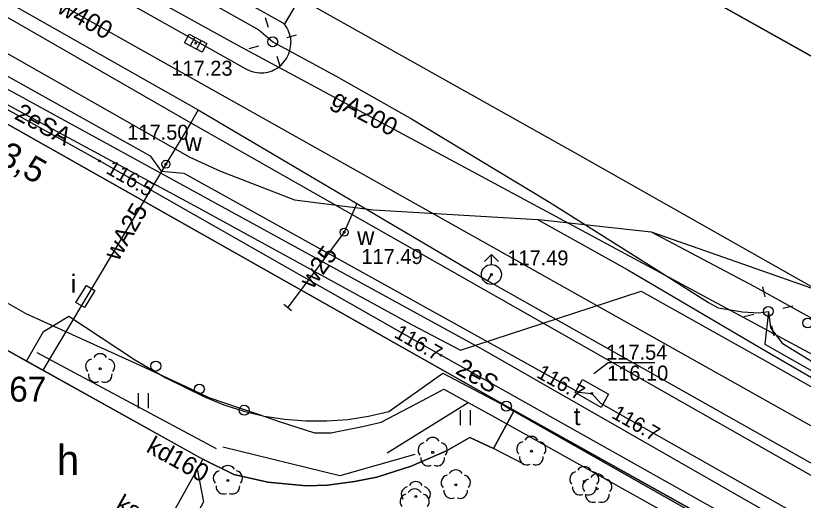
# Model space of a CAD drawing. Extents: x 6434771 to 6436222, y 5663454 to 5664782.
# Drawn here: x 6435316.51 to 6435355.97, y 5663796.64 to 5663820.92 of the extents above; entities that cross this region are included whole.
import ezdxf

# ---------------------------------------------------------------- set-up
doc = ezdxf.new("R2010")
doc.units = 0
for name, color, linetype in [('Warstwa 1', 7, 'Continuous'), ('Warstwa 10', 7, 'Continuous'), ('Warstwa 11', 7, 'Continuous'), ('Warstwa 12', 7, 'Continuous'), ('Warstwa 13', 7, 'Continuous'), ('Warstwa 14', 7, 'Continuous'), ('Warstwa 2', 7, 'Continuous'), ('Warstwa 20', 7, 'Continuous'), ('Warstwa 3', 7, 'Continuous'), ('Warstwa 4', 7, 'Continuous'), ('Warstwa 5', 7, 'Continuous'), ('Warstwa 6', 7, 'Continuous'), ('Warstwa 7', 7, 'Continuous'), ('Warstwa 8', 7, 'Continuous'), ('Warstwa 9', 7, 'Continuous')]:
    doc.layers.add(name, color=color, linetype=linetype)

msp = doc.modelspace()

# ---------------------------------------------------------------- linework, layer by layer
at = {"layer": 'Warstwa 1'}
for p, q in [((6435284.269, 5663833.48), (6435341.096, 5663801.352)), ((6435284.269, 5663833.48), (6435341.096, 5663801.352)), ((6435341.096, 5663801.352), (6435379.471, 5663779.947)), ((6435341.096, 5663801.352), (6435379.471, 5663779.947))]:
    msp.add_line(p, q, dxfattribs=at)
msp.add_lwpolyline([(6435315.15, 5663804.67), (6435325.88, 5663798.7), (6435322.44, 5663792.51), (6435311.73, 5663798.5), (6435312.37, 5663799.67), (6435312.69, 5663800.25), (6435314.19, 5663802.94), (6435314.51, 5663803.52)], close=True, dxfattribs=at)
for centre in [(6435323.53, 5663803.36), (6435325.71, 5663802.21), (6435327.96, 5663801.15)]:
    msp.add_circle(centre, 0.25, dxfattribs=at)
at = {"layer": 'Warstwa 10'}
for points in [[(6435276.398, 5663847.572), (6435285.481, 5663842.407), (6435289.025, 5663840.412), (6435288.717, 5663836.154), (6435288.46, 5663831.396), (6435296.942, 5663826.797), (6435314.148, 5663817.497), (6435325.665, 5663811.286), (6435336.38, 5663805.426), (6435338.792, 5663804.166), (6435347.854, 5663807.111), (6435354.232, 5663803.535), (6435364.384, 5663797.782), (6435371.56, 5663793.64)], [(6435362.27, 5663788.69), (6435362.41, 5663788.96), (6435362.84, 5663789.86), (6435340.58, 5663802.36), (6435337.82, 5663803.9), (6435320.71, 5663813.64), (6435309.18, 5663820.04), (6435307.2, 5663820.8), (6435302.95, 5663823.03), (6435301.33, 5663824.12), (6435299.2, 5663826.42), (6435293.53, 5663831.99), (6435290.73, 5663834.08), (6435287.63, 5663836.01), (6435276.336, 5663842.501)]]:
    msp.add_lwpolyline(points, dxfattribs=at)
msp.add_circle((6435341.096, 5663801.352), 0.25, dxfattribs=at)
msp.add_circle((6435341.096, 5663801.352), 0.25, dxfattribs=at)
at = {"layer": 'Warstwa 11'}
for centre in [(6435320.74, 5663803.23), (6435337.404, 5663799.038), (6435342.35, 5663799.09), (6435327.14, 5663797.63), (6435338.56, 5663797.41), (6435345, 5663797.58), (6435345.65, 5663797.21), (6435336.56, 5663796.82)]:
    msp.add_circle(centre, 0.05, dxfattribs=at)
for centre, start, end in [((6435320.383, 5663803.346), 102.1471, 221.8529), ((6435320.74, 5663803.605), 30.1471, 149.8529), ((6435321.097, 5663803.346), 318.1471, 77.8529), ((6435320.52, 5663802.927), 174.1471, 293.8529), ((6435320.96, 5663802.927), 246.1471, 5.8529), ((6435337.404, 5663799.413), 30.1471, 149.8529), ((6435342.35, 5663799.465), 30.1471, 149.8529), ((6435337.047, 5663799.154), 102.1471, 221.8529), ((6435337.761, 5663799.154), 318.1471, 77.8529), ((6435341.993, 5663799.206), 102.1471, 221.8529), ((6435342.707, 5663799.206), 318.1471, 77.8529), ((6435337.184, 5663798.735), 174.1471, 293.8529), ((6435337.624, 5663798.735), 246.1471, 5.8529), ((6435342.13, 5663798.787), 174.1471, 293.8529), ((6435342.57, 5663798.787), 246.1471, 5.8529), ((6435326.783, 5663797.746), 102.1471, 221.8529), ((6435327.14, 5663798.005), 30.1471, 149.8529), ((6435327.497, 5663797.746), 318.1471, 77.8529), ((6435338.56, 5663797.785), 30.1471, 149.8529), ((6435345, 5663797.955), 30.1471, 149.8529), ((6435338.203, 5663797.526), 102.1471, 221.8529), ((6435338.917, 5663797.526), 318.1471, 77.8529), ((6435344.643, 5663797.696), 102.1471, 221.8529), ((6435345.65, 5663797.585), 30.1471, 149.8529), ((6435345.357, 5663797.696), 318.1471, 77.8529), ((6435326.92, 5663797.327), 174.1471, 293.8529), ((6435327.36, 5663797.327), 246.1471, 5.8529), ((6435336.56, 5663797.195), 30.1471, 149.8529), ((6435344.78, 5663797.277), 174.1471, 293.8529), ((6435345.293, 5663797.326), 102.1471, 221.8529), ((6435345.22, 5663797.277), 246.1471, 5.8529), ((6435346.007, 5663797.326), 318.1471, 77.8529), ((6435336.143, 5663796.576), 102.1471, 221.8529), ((6435336.203, 5663796.936), 102.1471, 221.8529), ((6435336.5, 5663796.835), 30.1471, 149.8529), ((6435336.857, 5663796.576), 318.1471, 77.8529), ((6435336.917, 5663796.936), 318.1471, 77.8529), ((6435338.34, 5663797.107), 174.1471, 293.8529), ((6435338.78, 5663797.107), 246.1471, 5.8529), ((6435345.43, 5663796.907), 174.1471, 293.8529), ((6435345.87, 5663796.907), 246.1471, 5.8529)]:
    msp.add_arc(centre, 0.375, start, end, dxfattribs=at)
at = {"layer": 'Warstwa 12'}
for points in [[(6435496.272, 5663731.55), (6435494.673, 5663731.954), (6435441.98, 5663757.861), (6435431.505, 5663763.318), (6435395.21, 5663783.064), (6435393.025, 5663784.254), (6435327.584, 5663819.466), (6435304.485, 5663832.195), (6435292.223, 5663838.764), (6435285.521, 5663842.735), (6435276.408, 5663848.377)], [(6435276.372, 5663845.49), (6435313.12, 5663824.65), (6435397.7, 5663777.16), (6435400.08, 5663771.33), (6435444.75, 5663747.22)], [(6435276.356, 5663844.113), (6435325.654, 5663816.199), (6435333.608, 5663811.513), (6435340.162, 5663807.633), (6435364.946, 5663793.663), (6435394.798, 5663777.062), (6435394.937, 5663776.984)], [(6435286.42, 5663844), (6435287.35, 5663843.455), (6435292.961, 5663840.318), (6435298.714, 5663837.138), (6435303.419, 5663834.605), (6435305.745, 5663833.419), (6435306.683, 5663832.532), (6435308.014, 5663831.992), (6435310.819, 5663830.397), (6435322.822, 5663823.509), (6435328.691, 5663820.214), (6435329.386, 5663819.611), (6435332.564, 5663817.88), (6435336.345, 5663815.743), (6435343.262, 5663811.567), (6435348.084, 5663808.529), (6435351.234, 5663806.553), (6435351.715, 5663806.277), (6435352.923, 5663806.074), (6435353.729, 5663806.037), (6435354.225, 5663806.103)], [(6435276.308, 5663840.167), (6435285.47, 5663834.8), (6435286.134, 5663834.744), (6435286.62, 5663834.35), (6435323.25, 5663813.89), (6435323.79, 5663813.12), (6435324.94, 5663813.03), (6435344.71, 5663802.06), (6435345.376, 5663801.99), (6435345.82, 5663801.51), (6435374.05, 5663785.53), (6435381.33, 5663787.82), (6435417.36, 5663768.01), (6435438.98, 5663755.98), (6435463.27, 5663743.33), (6435463.498, 5663743.152), (6435463.77, 5663743.07), (6435464.82, 5663742.52), (6435490.42, 5663730.15), (6435500.39, 5663725.18)], [(6435276.296, 5663839.122), (6435282.733, 5663835.528), (6435283.155, 5663835.293), (6435283.578, 5663835.058), (6435339.95, 5663804.176), (6435373.154, 5663785.164), (6435373.6, 5663784.903), (6435374.09, 5663784.842), (6435381.569, 5663787.202), (6435381.966, 5663786.947), (6435382.363, 5663786.692), (6435416.468, 5663767.82), (6435452.468, 5663747.664), (6435497.181, 5663726.003), (6435502.116, 5663724.694), (6435541.028, 5663706.294), (6435541.516, 5663706.079), (6435555.51, 5663699.69), (6435571.692, 5663693.874), (6435578.552, 5663690.422)], [(6435293.228, 5663834.004), (6435325.286, 5663815.553), (6435364.64, 5663793.187), (6435394.601, 5663776.514), (6435437.403, 5663753.976), (6435437.705, 5663753.871), (6435459.328, 5663743.372)], [(6435325.654, 5663816.199), (6435325.286, 5663815.553), (6435324.031, 5663813.478), (6435317.862, 5663803.161)], [(6435301.381, 5663814.818), (6435304.531, 5663813.026), (6435312.56, 5663808.528), (6435317.022, 5663805.997), (6435322.544, 5663803.492), (6435325.031, 5663802.332), (6435326.182, 5663801.779), (6435327.709, 5663801.276), (6435328.664, 5663800.945), (6435329.709, 5663800.582), (6435331.487, 5663800.019), (6435332.294, 5663800.009), (6435333.884, 5663800.34), (6435334.816, 5663800.546), (6435336.575, 5663801.467), (6435337.956, 5663802.205), (6435340.361, 5663800.883), (6435352.831, 5663793.927), (6435371.59, 5663783.486), (6435371.373, 5663781.121), (6435370.67, 5663774.08)], [(6435333.608, 5663811.513), (6435332.961, 5663810.07), (6435330.135, 5663806.284)], [(6435340.162, 5663807.633), (6435340.346, 5663807.951)], [(6435354.225, 5663806.103), (6435354.045, 5663804.455)], [(6435354.225, 5663806.103), (6435354.045, 5663804.455), (6435378.698, 5663790.467), (6435402.889, 5663777.914), (6435418.826, 5663768.461), (6435428.67, 5663762.922)], [(6435354.225, 5663806.103), (6435354.339, 5663805.276), (6435354.921, 5663804.516), (6435356.256, 5663803.692), (6435357.591, 5663802.815), (6435361.586, 5663800.407), (6435364.82, 5663798.645), (6435367.626, 5663797.157), (6435374.185, 5663793.482), (6435378.033, 5663791.335), (6435380.136, 5663790.212), (6435385.102, 5663787.109), (6435386.865, 5663786.012), (6435388.176, 5663785.377), (6435390.525, 5663783.895), (6435393.123, 5663782.317), (6435393.63, 5663781.962), (6435398.309, 5663779.51), (6435408.093, 5663774.465), (6435411.635, 5663772.573), (6435418.397, 5663768.965), (6435423.022, 5663766.513), (6435428.828, 5663763.443)]]:
    msp.add_lwpolyline(points, dxfattribs=at)
at = {"layer": 'Warstwa 14'}
msp.add_lwpolyline([(6435348.529, 5663803.532), (6435346.196, 5663803.532), (6435345.484, 5663802.965)], dxfattribs=at)
for centre in [(6435320.71, 5663813.64), (6435337.82, 5663803.9), (6435345.376, 5663801.99), (6435345.376, 5663801.99), (6435345.376, 5663801.99)]:
    msp.add_circle(centre, 0.045, dxfattribs=at)
at = {"layer": 'Warstwa 2'}
msp.add_line((6435341.026, 5663801.362), (6435372.62, 5663783.46), dxfattribs=at)
for points in [[(6435341.476, 5663801.109), (6435340.455, 5663799.23)], [(6435340.455, 5663799.23), (6435339.262, 5663799.789), (6435338.088, 5663799.109), (6435336.324, 5663798.343), (6435334.597, 5663797.798), (6435333.487, 5663797.579), (6435332.134, 5663797.4), (6435331.061, 5663797.354), (6435329.135, 5663797.539), (6435327.431, 5663797.929), (6435325.88, 5663798.7)], [(6435341.97, 5663798.449), (6435340.455, 5663799.23)]]:
    msp.add_lwpolyline(points, dxfattribs=at)
for centre in [(6435329.386, 5663819.611), (6435354.225, 5663806.103), (6435356.2, 5663805.52)]:
    msp.add_circle(centre, 0.25, dxfattribs=at)
at = {"layer": 'Warstwa 20'}
msp.add_line((6435330.327, 5663806.124), (6435329.943, 5663806.444), dxfattribs=at)
at = {"layer": 'Warstwa 4'}
for p, q in [((6435325.49, 5663819.844), (6435325.252, 5663819.404)), ((6435325.798, 5663819.678), (6435325.56, 5663819.238))]:
    msp.add_line(p, q, dxfattribs=at)
for points in [[(6435329.174, 5663820.33), (6435329.032, 5663820.81)], [(6435330.105, 5663819.823), (6435330.585, 5663819.965)], [(6435328.667, 5663819.399), (6435328.187, 5663819.257)], [(6435329.598, 5663818.892), (6435329.74, 5663818.412)], [(6435339.992, 5663808.597), (6435340.346, 5663808.951)], [(6435340.7, 5663808.597), (6435340.346, 5663808.951)], [(6435340.346, 5663808.451), (6435340.346, 5663808.951)], [(6435320.474, 5663807.146), (6435319.953, 5663806.293), (6435319.526, 5663806.554), (6435320.047, 5663807.407), (6435320.474, 5663807.146)], [(6435354.063, 5663806.835), (6435353.956, 5663807.324)], [(6435354.957, 5663806.265), (6435355.446, 5663806.372)], [(6435353.493, 5663805.941), (6435353.004, 5663805.834)], [(6435354.387, 5663805.371), (6435354.494, 5663804.882)], [(6435326.577, 5663799.218), (6435317.577, 5663804.024)], [(6435339.183, 5663801.526), (6435335.123, 5663798.996)], [(6435336.51, 5663798.929), (6435332.749, 5663797.868), (6435326.894, 5663799.293)]]:
    msp.add_lwpolyline(points, dxfattribs=at)
for points in [[(6435325.204, 5663819.999), (6435326.084, 5663819.523), (6435325.846, 5663819.083), (6435324.966, 5663819.559)], [(6435344.539, 5663802.034), (6435344.909, 5663802.686), (6435346.213, 5663801.946), (6435345.843, 5663801.294)]]:
    msp.add_lwpolyline(points, close=True, dxfattribs=at)
for centre, radius in [((6435324.031, 5663813.478), 0.2), ((6435332.961, 5663810.07), 0.2), ((6435340.346, 5663807.951), 0.5)]:
    msp.add_circle(centre, radius, dxfattribs=at)
at = {"layer": 'Warstwa 5'}
for p, q in [((6435345.423, 5663825.041), (6435393.413, 5663798.15)), ((6435317.9, 5663805.1), (6435319.17, 5663805.86)), ((6435319.17, 5663805.86), (6435322.507, 5663803.664)), ((6435317.048, 5663803.614), (6435317.9, 5663805.1)), ((6435322.507, 5663803.664), (6435324.025, 5663802.777)), ((6435317.048, 5663803.614), (6435325.88, 5663798.7)), ((6435335.212, 5663801.083), (6435337.906, 5663803.01)), ((6435337.906, 5663803.01), (6435341.026, 5663801.362)), ((6435324.025, 5663802.777), (6435325.022, 5663802.286)), ((6435325.022, 5663802.286), (6435325.963, 5663801.816)), ((6435322.667, 5663801.249), (6435322.667, 5663801.999)), ((6435323.167, 5663801.249), (6435323.167, 5663801.999)), ((6435325.963, 5663801.816), (6435326.937, 5663801.421)), ((6435326.937, 5663801.421), (6435327.938, 5663801.101)), ((6435341.026, 5663801.362), (6435341.475, 5663801.107)), ((6435327.938, 5663801.101), (6435328.961, 5663800.859)), ((6435334.188, 5663800.846), (6435335.212, 5663801.083)), ((6435338.797, 5663800.398), (6435338.797, 5663801.148)), ((6435339.297, 5663800.398), (6435339.297, 5663801.148)), ((6435340.455, 5663799.23), (6435341.475, 5663801.107)), ((6435328.961, 5663800.859), (6435330, 5663800.695)), ((6435330, 5663800.695), (6435331.048, 5663800.612)), ((6435331.048, 5663800.612), (6435332.1, 5663800.61)), ((6435332.1, 5663800.61), (6435333.148, 5663800.688)), ((6435333.148, 5663800.688), (6435334.188, 5663800.846)), ((6435338.088, 5663799.109), (6435339.262, 5663799.789)), ((6435339.262, 5663799.789), (6435340.455, 5663799.23)), ((6435336.324, 5663798.343), (6435338.088, 5663799.109)), ((6435325.88, 5663798.7), (6435327.431, 5663797.929)), ((6435334.597, 5663797.798), (6435336.324, 5663798.343)), ((6435327.431, 5663797.929), (6435329.135, 5663797.539)), ((6435333.487, 5663797.579), (6435334.597, 5663797.798)), ((6435329.135, 5663797.539), (6435331.061, 5663797.354)), ((6435331.061, 5663797.354), (6435332.134, 5663797.4)), ((6435332.134, 5663797.4), (6435333.487, 5663797.579))]:
    msp.add_line(p, q, dxfattribs=at)
at = {"layer": 'Warstwa 6'}
for points in [[(6435557.624, 5663617.186), (6435560.245, 5663620.878), (6435595.767, 5663670.923), (6435531.111, 5663701.684), (6435473.15, 5663729.463), (6435470.997, 5663730.839), (6435385.94, 5663776.469), (6435383.505, 5663771.998), (6435381.775, 5663772.849), (6435379.415, 5663768.737), (6435374.588, 5663771.455), (6435379.471, 5663779.947), (6435341.096, 5663801.352), (6435284.269, 5663833.48), (6435246.778, 5663854.403), (6435242.169, 5663846.309), (6435237.4, 5663848.916), (6435241.929, 5663857.022), (6435210.691, 5663874.851), (6435202.784, 5663879.266), (6435199.977, 5663874.56), (6435180.355, 5663839.798)], [(6435246.778, 5663854.403), (6435284.269, 5663833.48), (6435341.096, 5663801.352), (6435379.471, 5663779.947)], [(6435345.423, 5663825.041), (6435393.413, 5663798.15)]]:
    msp.add_lwpolyline(points, dxfattribs=at)
for centre in [(6435325.525, 5663819.541), (6435324.031, 5663813.478), (6435332.961, 5663810.07), (6435340.346, 5663807.951), (6435345.376, 5663801.99)]:
    msp.add_circle(centre, 0.045, dxfattribs=at)
at = {"layer": 'Warstwa 7'}
msp.add_lwpolyline([(6435325.601, 5663798.197), (6435325.92, 5663796.56), (6435323.243, 5663791.591)], dxfattribs=at)
at = {"layer": 'Warstwa 8'}
for p, q in [((6435321.639, 5663825.164), (6435329.895, 5663820.569)), ((6435345.423, 5663825.041), (6435393.413, 5663798.15)), ((6435319.462, 5663823.08), (6435328.012, 5663818.275)), ((6435311.189, 5663821.796), (6435325.241, 5663813.829)), ((6435329.973, 5663820.476), (6435330.747, 5663821.797)), ((6435329.974, 5663820.476), (6435330.747, 5663821.797)), ((6435330.747, 5663821.797), (6435344.539, 5663814.043)), ((6435330.747, 5663821.797), (6435344.539, 5663814.043)), ((6435329.895, 5663820.569), (6435329.965, 5663820.487)), ((6435329.965, 5663820.487), (6435329.974, 5663820.476)), ((6435329.973, 5663820.476), (6435330.029, 5663820.401)), ((6435330.029, 5663820.401), (6435330.087, 5663820.311)), ((6435330.087, 5663820.311), (6435330.138, 5663820.216)), ((6435330.138, 5663820.216), (6435330.182, 5663820.118)), ((6435330.182, 5663820.118), (6435330.218, 5663820.018)), ((6435330.218, 5663820.018), (6435330.248, 5663819.914)), ((6435330.248, 5663819.914), (6435330.27, 5663819.81)), ((6435330.27, 5663819.81), (6435330.285, 5663819.703)), ((6435330.282, 5663819.382), (6435330.291, 5663819.489)), ((6435330.285, 5663819.703), (6435330.292, 5663819.596)), ((6435330.291, 5663819.489), (6435330.292, 5663819.596)), ((6435330.173, 5663818.968), (6435330.212, 5663819.069)), ((6435330.212, 5663819.069), (6435330.243, 5663819.171)), ((6435330.243, 5663819.171), (6435330.266, 5663819.276)), ((6435330.266, 5663819.276), (6435330.282, 5663819.382)), ((6435329.952, 5663818.602), (6435330.017, 5663818.688)), ((6435330.017, 5663818.688), (6435330.076, 5663818.777)), ((6435330.076, 5663818.777), (6435330.128, 5663818.871)), ((6435330.128, 5663818.871), (6435330.173, 5663818.968)), ((6435328.012, 5663818.275), (6435328.106, 5663818.222)), ((6435329.451, 5663818.206), (6435329.545, 5663818.257)), ((6435329.545, 5663818.257), (6435329.636, 5663818.314)), ((6435329.636, 5663818.314), (6435329.723, 5663818.377)), ((6435329.723, 5663818.377), (6435329.805, 5663818.447)), ((6435329.805, 5663818.447), (6435329.881, 5663818.522)), ((6435329.881, 5663818.522), (6435329.952, 5663818.602)), ((6435328.106, 5663818.222), (6435328.203, 5663818.176)), ((6435328.203, 5663818.176), (6435328.303, 5663818.138)), ((6435328.303, 5663818.138), (6435328.405, 5663818.106)), ((6435328.405, 5663818.106), (6435328.51, 5663818.082)), ((6435328.51, 5663818.082), (6435328.616, 5663818.065)), ((6435328.616, 5663818.065), (6435328.723, 5663818.056)), ((6435328.723, 5663818.056), (6435328.83, 5663818.055)), ((6435328.83, 5663818.055), (6435328.937, 5663818.062)), ((6435328.937, 5663818.062), (6435329.044, 5663818.076)), ((6435329.044, 5663818.076), (6435329.149, 5663818.097)), ((6435329.149, 5663818.097), (6435329.252, 5663818.126)), ((6435329.252, 5663818.126), (6435329.353, 5663818.163)), ((6435329.353, 5663818.163), (6435329.451, 5663818.206)), ((6435344.539, 5663814.043), (6435356.736, 5663807.152)), ((6435344.539, 5663814.043), (6435356.736, 5663807.152)), ((6435325.241, 5663813.829), (6435326.77, 5663813.12)), ((6435326.77, 5663813.12), (6435330.48, 5663811.69)), ((6435330.48, 5663811.69), (6435334.43, 5663811.19)), ((6435334.43, 5663811.19), (6435342.655, 5663810.708)), ((6435342.655, 5663810.708), (6435342.727, 5663810.704)), ((6435342.727, 5663810.704), (6435348.36, 5663810.08)), ((6435348.36, 5663810.08), (6435350.684, 5663809.278)), ((6435350.684, 5663809.278), (6435356.736, 5663807.152))]:
    msp.add_line(p, q, dxfattribs=at)
at = {"layer": 'Warstwa 9'}
for p, q in [((6435321.639, 5663825.164), (6435329.895, 5663820.569)), ((6435319.462, 5663823.08), (6435328.012, 5663818.275)), ((6435311.189, 5663821.796), (6435325.241, 5663813.829)), ((6435329.895, 5663820.569), (6435329.965, 5663820.487)), ((6435329.965, 5663820.487), (6435329.973, 5663820.476)), ((6435329.973, 5663820.476), (6435330.029, 5663820.401)), ((6435330.029, 5663820.401), (6435330.087, 5663820.311)), ((6435330.087, 5663820.311), (6435330.138, 5663820.216)), ((6435330.138, 5663820.216), (6435330.182, 5663820.118)), ((6435330.182, 5663820.118), (6435330.218, 5663820.018)), ((6435330.218, 5663820.018), (6435330.248, 5663819.914)), ((6435330.248, 5663819.914), (6435330.27, 5663819.81)), ((6435330.27, 5663819.81), (6435330.285, 5663819.703)), ((6435330.282, 5663819.382), (6435330.291, 5663819.489)), ((6435330.285, 5663819.703), (6435330.292, 5663819.596)), ((6435330.291, 5663819.489), (6435330.292, 5663819.596)), ((6435330.173, 5663818.968), (6435330.212, 5663819.069)), ((6435330.212, 5663819.069), (6435330.243, 5663819.171)), ((6435330.243, 5663819.171), (6435330.266, 5663819.276)), ((6435330.266, 5663819.276), (6435330.282, 5663819.382)), ((6435329.952, 5663818.602), (6435330.017, 5663818.688)), ((6435330.017, 5663818.688), (6435330.076, 5663818.777)), ((6435330.076, 5663818.777), (6435330.128, 5663818.871)), ((6435330.128, 5663818.871), (6435330.173, 5663818.968)), ((6435328.012, 5663818.275), (6435328.106, 5663818.222)), ((6435329.451, 5663818.206), (6435329.545, 5663818.257)), ((6435329.545, 5663818.257), (6435329.636, 5663818.314)), ((6435329.636, 5663818.314), (6435329.723, 5663818.377)), ((6435329.723, 5663818.377), (6435329.805, 5663818.447)), ((6435329.805, 5663818.447), (6435329.881, 5663818.522)), ((6435329.881, 5663818.522), (6435329.952, 5663818.602)), ((6435328.106, 5663818.222), (6435328.203, 5663818.176)), ((6435328.203, 5663818.176), (6435328.303, 5663818.138)), ((6435328.303, 5663818.138), (6435328.405, 5663818.106)), ((6435328.405, 5663818.106), (6435328.51, 5663818.082)), ((6435328.51, 5663818.082), (6435328.616, 5663818.065)), ((6435328.616, 5663818.065), (6435328.723, 5663818.056)), ((6435328.723, 5663818.056), (6435328.83, 5663818.055)), ((6435328.83, 5663818.055), (6435328.937, 5663818.062)), ((6435328.937, 5663818.062), (6435329.044, 5663818.076)), ((6435329.044, 5663818.076), (6435329.149, 5663818.097)), ((6435329.149, 5663818.097), (6435329.252, 5663818.126)), ((6435329.252, 5663818.126), (6435329.353, 5663818.163)), ((6435329.353, 5663818.163), (6435329.451, 5663818.206)), ((6435325.241, 5663813.829), (6435326.77, 5663813.12)), ((6435326.77, 5663813.12), (6435330.48, 5663811.69)), ((6435330.48, 5663811.69), (6435334.43, 5663811.19)), ((6435334.43, 5663811.19), (6435342.655, 5663810.708)), ((6435342.655, 5663810.708), (6435347.176, 5663808.176)), ((6435348.36, 5663810.08), (6435350.684, 5663809.278)), ((6435348.36, 5663810.08), (6435353.534, 5663807.343)), ((6435350.684, 5663809.278), (6435356.736, 5663807.152)), ((6435347.176, 5663808.176), (6435353.795, 5663804.286)), ((6435353.534, 5663807.343), (6435359.939, 5663803.801)), ((6435317.9, 5663805.1), (6435319.17, 5663805.86)), ((6435319.17, 5663805.86), (6435322.507, 5663803.664)), ((6435317.048, 5663803.614), (6435317.9, 5663805.1)), ((6435315.15, 5663804.67), (6435317.048, 5663803.614)), ((6435353.795, 5663804.286), (6435363.712, 5663798.545)), ((6435322.507, 5663803.664), (6435324.025, 5663802.777)), ((6435335.212, 5663801.083), (6435337.906, 5663803.01)), ((6435337.906, 5663803.01), (6435341.026, 5663801.362)), ((6435324.025, 5663802.777), (6435325.022, 5663802.286)), ((6435325.022, 5663802.286), (6435325.963, 5663801.816)), ((6435325.963, 5663801.816), (6435326.937, 5663801.421)), ((6435326.937, 5663801.421), (6435327.938, 5663801.101)), ((6435341.026, 5663801.362), (6435341.475, 5663801.107)), ((6435327.938, 5663801.101), (6435328.961, 5663800.859)), ((6435334.188, 5663800.846), (6435335.212, 5663801.083)), ((6435341.475, 5663801.107), (6435372.62, 5663783.46)), ((6435328.961, 5663800.859), (6435330, 5663800.695)), ((6435330, 5663800.695), (6435331.048, 5663800.612)), ((6435331.048, 5663800.612), (6435332.1, 5663800.61)), ((6435332.1, 5663800.61), (6435333.148, 5663800.688)), ((6435333.148, 5663800.688), (6435334.188, 5663800.846))]:
    msp.add_line(p, q, dxfattribs=at)

# ---------------------------------------------------------------- texts
at = {"layer": 'Warstwa 10'}
msp.add_text('1067', height=1.25, dxfattribs=at).set_placement((6435314.323, 5663801.58))
at = {"layer": 'Warstwa 11'}
for s, rotation, p in [('2eSA', 331.6623, (6435316.389, 5663815.778)), ('2eS', 330.8373, (6435338.493, 5663803.009))]:
    msp.add_text(s, height=0.9, rotation=rotation, dxfattribs=at).set_placement(p)
at = {"layer": 'Warstwa 13'}
for s, rotation, p in [('w400', 330.6883, (6435318.519, 5663821.102)), ('gA200', 331.9087, (6435332.263, 5663816.49)), ('wA25', 59.8168, (6435321.646, 5663808.576)), ('w25', 53.9554, (6435331.386, 5663807.175))]:
    msp.add_text(s, height=0.9, rotation=rotation, dxfattribs=at).set_placement(p)
at = {"layer": 'Warstwa 14'}
for s, height, rotation, p in [('1,3,5', 1.25, 330.5164, (6435314.34, 5663814.279)), ('116.5', 0.75, 330.3503, (6435320.978, 5663813.056)), ('116.7', 0.75, 330.3503, (6435335.418, 5663804.836)), ('116.7', 0.75, 330.9748, (6435342.555, 5663802.827)), ('116.7', 0.75, 330.4878, (6435346.323, 5663800.795))]:
    msp.add_text(s, height=height, rotation=rotation, dxfattribs=at).set_placement(p)
msp.add_text('116.10', height=0.75, dxfattribs=at).set_placement((6435346.141, 5663802.634))
at = {"layer": 'Warstwa 3'}
msp.add_text('h', height=1.5, dxfattribs=at).set_placement((6435318.57, 5663797.903))
at = {"layer": 'Warstwa 5'}
for s, p in [('w', (6435324.967, 5663814.139)), ('w', (6435333.614, 5663809.427)), ('i', (6435319.27, 5663807.036)), ('t', (6435344.475, 5663800.397))]:
    msp.add_text(s, height=0.9, dxfattribs=at).set_placement(p)
at = {"layer": 'Warstwa 6'}
for s, p in [('117.23', (6435324.307, 5663817.912)), ('117.50', (6435322.098, 5663814.704)), ('117.49', (6435333.83, 5663808.475)), ('117.49', (6435341.14, 5663808.408)), ('117.54', (6435346.096, 5663803.679))]:
    msp.add_text(s, height=0.75, dxfattribs=at).set_placement(p)
at = {"layer": 'Warstwa 7'}
for s, p in [('kd160', (6435322.993, 5663799.098)), ('ks160', (6435321.436, 5663796.192))]:
    msp.add_text(s, height=0.9, rotation=330.9347, dxfattribs=at).set_placement(p)

doc.saveas('drawing.dxf')
